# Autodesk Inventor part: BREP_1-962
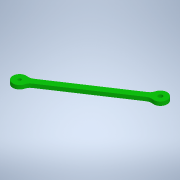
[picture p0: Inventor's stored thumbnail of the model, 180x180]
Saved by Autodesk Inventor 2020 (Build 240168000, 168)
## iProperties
Created: 2017-09
Part Number: BREP_1-962
Material: Générique
Document SubType Name: Modeling
Designer: bruno
Density: 1 g/cm^3
Appearance: Vert foncé
Mass: 7.11162 g
Surface Area: 46.5566 cm^2
Volume: 7.11162 cm^3
Sending System: SolidWorks 2016
Author: bruno
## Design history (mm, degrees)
feature "Importée1"
node "Solide1"
